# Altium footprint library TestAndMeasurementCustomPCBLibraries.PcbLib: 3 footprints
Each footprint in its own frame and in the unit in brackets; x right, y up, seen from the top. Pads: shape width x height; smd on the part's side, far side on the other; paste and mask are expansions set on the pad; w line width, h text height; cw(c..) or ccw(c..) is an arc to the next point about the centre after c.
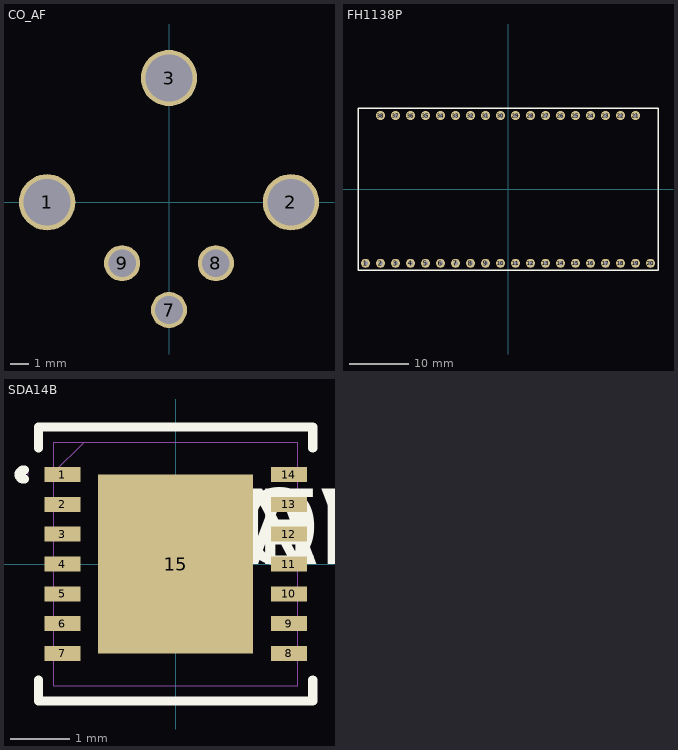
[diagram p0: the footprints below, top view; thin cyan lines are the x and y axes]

## CO_AF [mil]
pads (6):
  round 120 hole 100: 1(-260,0) 2(260,0) 3(0,265)
  round 76.93 hole 59.06: 7(0,-230) 8(100,-130) 9(-100,-130)
3D body: height 689.61, standoff 40, extent -346.53,-323.63 359.34,383.64

## FH1138P [mil]
pads (38):
  round 60 hole 30: 1(-950,-492.5) 2(-850,-492.5) 3(-750,-492.5) 4(-650,-492.5) 5(-550,-492.5) 6(-450,-492.5) 7(-350,-492.5) 8(-250,-492.5) 9(-150,-492.5) 10(-50,-492.5) 11(50,-492.5) 12(150,-492.5) 13(250,-492.5) 14(350,-492.5) 15(450,-492.5) 16(550,-492.5) 17(650,-492.5) 18(750,-492.5) 19(850,-492.5) 20(950,-492.5) 21(850,492.5) 22(750,492.5) 23(650,492.5) 24(550,492.5) 25(450,492.5) 26(350,492.5) 27(250,492.5) 28(150,492.5) 29(50,492.5) 30(-50,492.5) 31(-150,492.5) 32(-250,492.5) 33(-350,492.5) 34(-450,492.5) 35(-550,492.5) 36(-650,492.5) 37(-750,492.5) 38(-850,492.5)
Top Overlay:
  lines w10: -1000,-537.5 -1000,542.5 1000,542.5 1000,-537.5 -1000,-537.5
3D body: height 202.05, standoff -177.31, extent -1080.35,-501.13 1085,511.13

## SDA14B [mm]
pads (15):
  rect 0.6x0.25 smd paste-0.125: 1(-1.9,1.5) 2(-1.9,1) 3(-1.9,0.5) 4(-1.9,0) 5(-1.9,-0.5) 6(-1.9,-1) 7(-1.9,-1.5) 8(1.9,-1.5) 9(1.9,-1) 10(1.9,-0.5) 11(1.9,0) 12(1.9,0.5) 13(1.9,1) 14(1.9,1.5)
  rect 2.6x3 smd paste-1.3: 15(0,0)
Top Overlay:
  lines w0.152: -2.533,1.426 cw(c-2.552,1.5) -2.533,1.574 ; -2.299,-1.943 -2.299,-2.299 2.299,-2.299 2.299,-1.943 ; -2.299,1.943 -2.299,2.299 2.299,2.299 2.299,1.943
  text "TOL" at 0,0 h1.27
  text "VAL" at 0,0 h1.27
  text "DEV" at 0,0 h1.27
  text "PN" at 0,0 h1.27
Top Paste:
  region: 1.2,-0.1 0.1,-0.1 0.1,-1.4 1.2,-1.4
  region: 1.2,1.4 0.1,1.4 0.1,0.1 1.2,0.1
  region: -0.1,-0.1 -1.2,-0.1 -1.2,-1.4 -0.1,-1.4
  region: -0.1,1.4 -1.2,1.4 -1.2,0.1 -0.1,0.1
  region: 2.403,1.625 1.803,1.625 1.803,1.375 2.403,1.375
  region: 2.403,1.125 1.803,1.125 1.803,0.875 2.403,0.875
  region: 2.403,0.625 1.803,0.625 1.803,0.375 2.403,0.375
  region: 2.403,0.125 1.803,0.125 1.803,-0.125 2.403,-0.125
  region: 2.403,-0.375 1.803,-0.375 1.803,-0.625 2.403,-0.625
  region: 2.403,-0.875 1.803,-0.875 1.803,-1.125 2.403,-1.125
  region: 2.403,-1.375 1.803,-1.375 1.803,-1.625 2.403,-1.625
  region: -1.803,-1.375 -2.403,-1.375 -2.403,-1.625 -1.803,-1.625
  region: -1.803,-0.875 -2.403,-0.875 -2.403,-1.125 -1.803,-1.125
  region: -1.803,-0.375 -2.403,-0.375 -2.403,-0.625 -1.803,-0.625
  region: -1.803,0.125 -2.403,0.125 -2.403,-0.125 -1.803,-0.125
  region: -1.803,0.625 -2.403,0.625 -2.403,0.375 -1.803,0.375
  region: -1.803,1.125 -2.403,1.125 -2.403,0.875 -1.803,0.875
  region: -1.803,1.625 -2.403,1.625 -2.403,1.375 -1.803,1.375
Mechanical 1:
  circle w0: c-2.552,1.5 r0.076
  lines w0: -2.045,1.537 -1.537,2.045 ; -2.045,-2.045 -2.045,2.045 2.045,2.045 2.045,-2.045 -2.045,-2.045
  text "RefDes2" at 0,0 h1.27
3D body: height 0.8, standoff 0, extent -2,-2 2,2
